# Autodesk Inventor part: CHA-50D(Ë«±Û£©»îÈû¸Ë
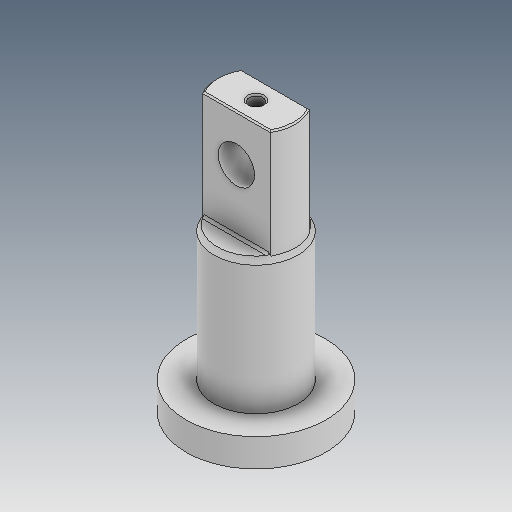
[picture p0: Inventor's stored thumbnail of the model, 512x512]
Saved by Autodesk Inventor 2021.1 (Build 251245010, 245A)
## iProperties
Created: 2019-12
Part Number: CHA-50D(Ë«±Û£©»îÈû¸Ë
Material: Ogólny
Document SubType Name: Modeling
Designer: user
Density: 1 g/cm^3
Appearance: Domyślna
Author: user
Revision Number: ÈÎºÎ
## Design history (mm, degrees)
feature "ÊäÈë1"
node "Bryła1"
